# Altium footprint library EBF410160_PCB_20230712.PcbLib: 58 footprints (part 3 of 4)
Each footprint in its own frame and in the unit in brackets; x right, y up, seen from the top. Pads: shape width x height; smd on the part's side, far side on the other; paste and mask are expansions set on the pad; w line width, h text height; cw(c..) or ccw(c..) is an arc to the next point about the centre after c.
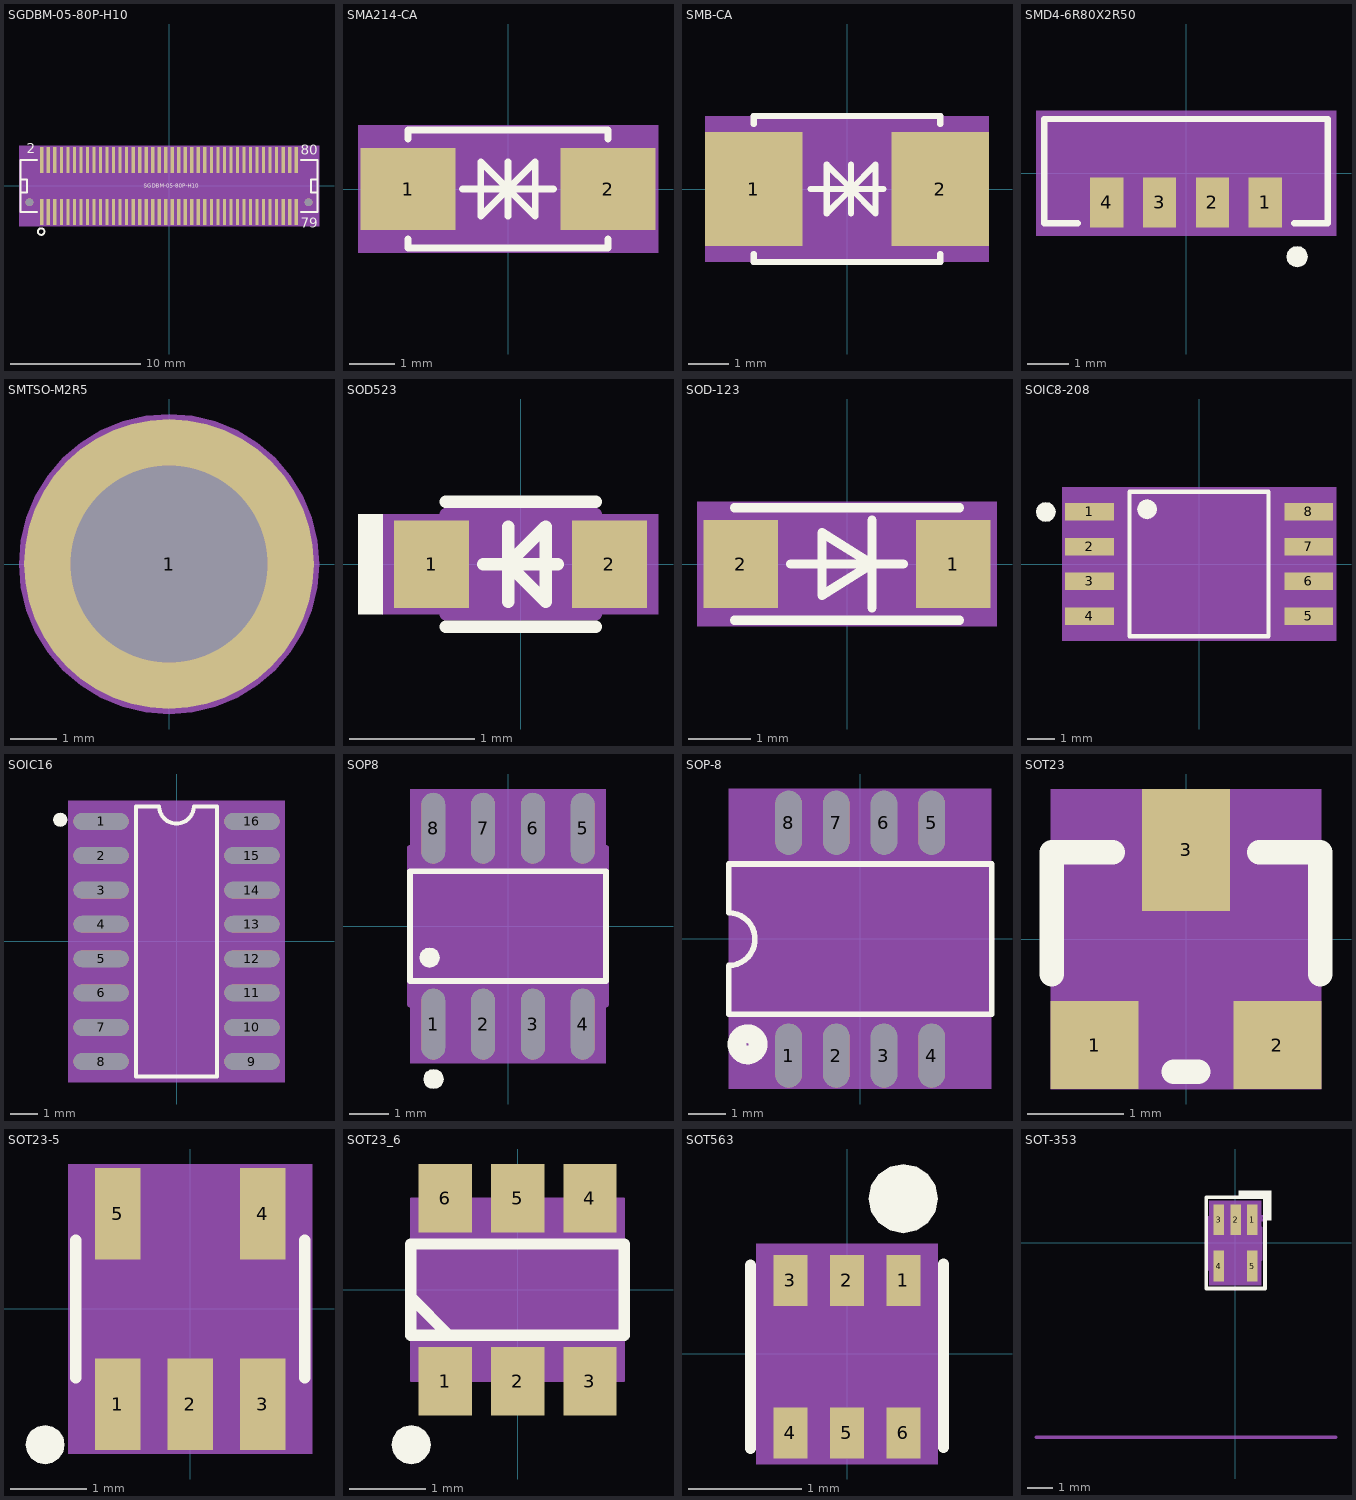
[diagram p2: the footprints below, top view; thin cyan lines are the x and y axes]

## SGDBM-05-80P-H10 [mm] "SGDBM-05-80P-H10"
pads (82):
  rect 0.25x2 smd: 1(-9.75,-2) 2(-9.75,2) 3(-9.25,-2) 4(-9.25,2) 5(-8.75,-2) 6(-8.75,2) 7(-8.25,-2) 8(-8.25,2) 9(-7.75,-2) 10(-7.75,2) 11(-7.25,-2) 12(-7.25,2) 13(-6.75,-2) 14(-6.75,2) 15(-6.25,-2) 16(-6.25,2) 17(-5.75,-2) 18(-5.75,2) 19(-5.25,-2) 20(-5.25,2) 21(-4.75,-2) 22(-4.75,2) 23(-4.25,-2) 24(-4.25,2) 25(-3.75,-2) 26(-3.75,2) 27(-3.25,-2) 28(-3.25,2) 29(-2.75,-2) 30(-2.75,2) 31(-2.25,-2) 32(-2.25,2) 33(-1.75,-2) 34(-1.75,2) 35(-1.25,-2) 36(-1.25,2) 37(-0.75,-2) 38(-0.75,2) 39(-0.25,-2) 40(-0.25,2) 41(0.25,-2) 42(0.25,2) 43(0.75,-2) 44(0.75,2) 45(1.25,-2) 46(1.25,2) 47(1.75,-2) 48(1.75,2) 49(2.25,-2) 50(2.25,2) 51(2.75,-2) 52(2.75,2) 53(3.25,-2) 54(3.25,2) 55(3.75,-2) 56(3.75,2) 57(4.25,-2) 58(4.25,2) 59(4.75,-2) 60(4.75,2) 61(5.25,-2) 62(5.25,2) 63(5.75,-2) 64(5.75,2) 65(6.25,-2) 66(6.25,2) 67(6.75,-2) 68(6.75,2) 69(7.25,-2) 70(7.25,2) 71(7.75,-2) 72(7.75,2) 73(8.25,-2) 74(8.25,2) 75(8.75,-2) 76(8.75,2) 77(9.25,-2) 78(9.25,2) 79(9.75,-2) 80(9.75,2)
  round 0.6 hole 0.6 unplated: ""(-10.7,-1.25) ""(10.7,-1.25)
Top Overlay:
  circle w0.15: c-9.8,-3.5 r0.25
  lines w0.15: -11.4,0 -11.4,-0.5 -10.9,-0.5 -10.9,0.5 -11.4,0.5 ; -10.1,-2 -11.4,-2 -11.4,2 -10.1,2 ; 10.1,-2 11.4,-2 11.4,2 10.1,2 ; 11.4,0 11.4,-0.5 10.9,-0.5 10.9,0.5 11.4,0.5
  text "80" at 10.113,2.399 h0.76
  text "79" at 10.113,-3.189 h0.76
  text "2" at -10.893,2.526 h0.76
  text "SGDBM-05-80P-H10" at -1.951,-0.152 h0.3
Top 3D Body:
  region: -11.5,3.1 -11.5,-3.1 11.5,-3.1 11.5,3.1
Mechanical 20:
  text "1" at -10.004,-2 h0.64
  text "3" at -9.504,-2 h0.64
  text "5" at -9.004,-2 h0.64
  text "2" at -10.004,2 h0.64
  text "4" at -9.504,2 h0.64
  text "6" at -9.004,2 h0.64
  text "38" at -1.258,2 h0.64
  text "34" at -2.258,2 h0.64
  text "36" at -1.758,2 h0.64
  text "80" at 9.242,2 h0.64
  text "46" at 0.742,2 h0.64
  text "28" at -3.758,2 h0.64
  text "25" at -4.258,-2 h0.64
  text "22" at -5.258,2 h0.64
  text "24" at -4.758,2 h0.64
  text "48" at 1.242,2 h0.64
  text "30" at -3.258,2 h0.64
  text "54" at 2.742,2 h0.64
  text "60" at 4.242,2 h0.64
  text "58" at 3.742,2 h0.64
  text "64" at 5.242,2 h0.64
  text "62" at 4.742,2 h0.64
  text "11" at -7.758,-2 h0.64
  text "13" at -7.258,-2 h0.64
  text "52" at 2.242,2 h0.64
  text "15" at -6.758,-2 h0.64
  text "17" at -6.258,-2 h0.64
  text "19" at -5.758,-2 h0.64
  text "21" at -5.258,-2 h0.64
  text "12" at -7.758,2 h0.64
  text "14" at -7.258,2 h0.64
  text "44" at 0.242,2 h0.64
  text "29" at -3.258,-2 h0.64
  text "42" at -0.258,2 h0.64
  text "7" at -8.504,-2 h0.64
  text "9" at -8.004,-2 h0.64
  text "23" at -4.758,-2 h0.64
  text "31" at -2.758,-2 h0.64
  text "49" at 1.742,-2 h0.64
  text "67" at 6.242,-2 h0.64
  text "73" at 7.742,-2 h0.64
  text "8" at -8.504,2 h0.64
  text "10" at -8.258,2 h0.64
  text "16" at -6.758,2 h0.64
  text "20" at -5.758,2 h0.64
  text "26" at -4.258,2 h0.64
  text "32" at -2.758,2 h0.64
  text "40" at -0.758,2 h0.64
  text "50" at 1.742,2 h0.64
  text "56" at 3.242,2 h0.64
  text "66" at 5.742,2 h0.64
  text "76" at 8.242,2 h0.64
  text "39" at -0.758,-2 h0.64
  text "78" at 8.742,2 h0.64
  text "45" at 0.742,-2 h0.64
  text "18" at -6.258,2 h0.64
  text "27" at -3.758,-2 h0.64
  text "37" at -1.258,-2 h0.64
  text "79" at 9.242,-2 h0.64
  text "77" at 8.742,-2 h0.64
  text "75" at 8.242,-2 h0.64
  text "74" at 7.742,2 h0.64
  text "72" at 7.242,2 h0.64
  text "71" at 7.242,-2 h0.64
  text "70" at 6.742,2 h0.64
  text "69" at 6.742,-2 h0.64
  text "68" at 6.242,2 h0.64
  text "65" at 5.742,-2 h0.64
  text "63" at 5.242,-2 h0.64
  text "61" at 4.742,-2 h0.64
  text "59" at 4.242,-2 h0.64
  text "57" at 3.742,-2 h0.64
  text "55" at 3.242,-2 h0.64
  text "53" at 2.742,-2 h0.64
  text "51" at 2.242,-2 h0.64
  text "33" at -2.258,-2 h0.64
  text "43" at 0.242,-2 h0.64
  text "41" at -0.258,-2 h0.64
  text "35" at -1.758,-2 h0.64
  text "47" at 1.242,-2 h0.64
Top Assembly:
  lines w0.15: -11.4,-2 -11.4,2 11.4,2 11.4,-2 -11.4,-2
3D body: height 3.81, standoff 0, extent -11.5,-3.1 11.5,3.1

## SMA214-CA [mm] "SMA214-CA"
pads (2):
  rect 2.1x1.8 smd: 1(-2.2,0) 2(2.2,0)
Top Overlay:
  lines w0.15: -2.2,-1.1 -2.2,-1.3 2.2,-1.3 2.2,-1.1 ; -2.2,1.1 -2.2,1.3 2.2,1.3 2.2,1.1 ; -1,0 1,0 ; 0,-0.6 0,0.6 ; 0,0 0.6,-0.6 0.6,0.6 0,0 ; 0,0 -0.6,0.6 -0.6,-0.6 0,0
Top 3D Body:
  region: -3.3,1.4 -3.3,-1.4 3.3,-1.4 3.3,1.4
Mechanical 20:
  text "1" at -1.946,0 h0.64
  text "2" at 2.454,0 h0.64
Top Assembly:
  lines w0.15: -2.2,-1.25 -2.2,1.25 2.2,1.25 2.2,-1.25 -2.2,-1.25
3D body: height 3.81, standoff 0, extent -3.3,-1.4 3.3,1.4

## SMB-CA [mm] "SMB-CA"
pads (2):
  rect 2.4x2.8 smd: 1(-2.3,0) 2(2.3,0)
Top Overlay:
  lines w0.15: -2.3,-1.6 -2.3,-1.8 2.3,-1.8 2.3,-1.6 ; -2.3,1.6 -2.3,1.8 2.3,1.8 2.3,1.6 ; -0.9,0 0.9,0 ; 0.1,0 -0.5,0.6 -0.5,-0.6 0.1,0 ; 0.1,0 0.7,-0.6 0.7,0.6 0.1,0 ; 0.1,-0.6 0.1,0.6 0.1,-0.6
Top 3D Body:
  region: -3.5,1.8 -3.5,-1.8 3.5,-1.8 3.5,1.8
Mechanical 20:
  text "2" at 2.3,0.254 h0.64
  text "1" at -2.3,0.254 h0.64
Top Assembly:
  lines w0.15: -2.3,-1.8 -2.3,1.8 2.3,1.8 2.3,-1.8 -2.3,-1.8
3D body: height 3.81, standoff 0, extent -3.5,-1.8 3.5,1.8

## SMD4-6R80X2R50 [mm] "SMD4-6R80X2R50"
pads (4):
  rect 0.8x1.2 smd: 1(1.905,-0.7) 2(0.635,-0.7) 3(-0.635,-0.7) 4(-1.905,-0.7)
Top Overlay:
  dashed: 2.412,-2.002 2.431,-2.1 2.487,-2.182 2.569,-2.238 2.667,-2.257 2.764,-2.238 2.792,-2.219 2.847,-2.182 2.902,-2.1 2.922,-2.002 2.902,-1.904 2.847,-1.822 2.792,-1.785 2.764,-1.766 2.667,-1.747 2.569,-1.766 2.487,-1.822 2.431,-1.904
  lines w0.15: -2.6,-1.2 -3.4,-1.2 -3.4,1.3 3.4,1.3 3.4,-1.2 2.6,-1.2
Top 3D Body:
  region: -3.6,1.5 -3.6,-1.5 3.6,-1.5 3.6,1.5
Mechanical 20:
  text "2" at 0.889,-0.7 h0.64
  text "3" at -0.381,-0.7 h0.64
  text "4" at -1.651,-0.7 h0.64
  text "1" at 2.159,-0.7 h0.64
Top Assembly:
  lines w0.15: -3.4,-1.2 -3.4,1.3 3.4,1.3 3.4,-1.2 -3.4,-1.2
3D body: height 3.81, standoff 0, extent -3.6,-1.5 3.6,1.5

## SMTSO-M2R5 [mm] "SMTSO-M2R5"
pads (1):
  round 6.2 / inner round 5.2 / far side round 5.2 hole 4.22: 1(0,0)
Top Overlay:
  text "M2.5X4mm" at -0.94,0.646 h0.3
Top Paste:
  dashed: 3.074,0.4 2.072,0.4 2.029,0.579 1.971,0.754 1.898,0.923 1.81,1.084 1.709,1.238 1.594,1.382 1.468,1.516 1.33,1.638 1.182,1.748 1.025,1.844 0.861,1.926 0.689,1.994 0.513,2.047 0.4,2.072 0.4,3.074 0.666,3.028 0.928,2.958 1.182,2.866 1.427,2.752 1.662,2.617 1.883,2.462 2.091,2.289 2.282,2.098 2.457,1.891 2.612,1.67 2.748,1.436 2.862,1.191 2.955,0.937 3.026,0.676 3.073,0.409
  dashed: 0.4,-3.074 0.4,-2.072 0.579,-2.029 0.754,-1.971 0.923,-1.898 1.084,-1.81 1.238,-1.709 1.382,-1.594 1.516,-1.468 1.638,-1.33 1.748,-1.182 1.844,-1.025 1.926,-0.861 1.994,-0.689 2.047,-0.513 2.072,-0.4 3.074,-0.4 3.028,-0.666 2.958,-0.928 2.866,-1.182 2.752,-1.427 2.617,-1.662 2.462,-1.883 2.289,-2.091 2.098,-2.282 1.891,-2.457 1.67,-2.612 1.436,-2.748 1.191,-2.862 0.937,-2.955 0.676,-3.026 0.409,-3.073
  dashed: -3.074,-0.4 -2.072,-0.4 -2.029,-0.579 -1.971,-0.754 -1.898,-0.923 -1.81,-1.084 -1.709,-1.238 -1.594,-1.382 -1.468,-1.516 -1.33,-1.638 -1.182,-1.748 -1.025,-1.844 -0.861,-1.926 -0.689,-1.994 -0.513,-2.047 -0.4,-2.072 -0.4,-3.074 -0.666,-3.028 -0.928,-2.958 -1.182,-2.866 -1.427,-2.752 -1.662,-2.617 -1.883,-2.462 -2.091,-2.289 -2.282,-2.098 -2.457,-1.891 -2.612,-1.67 -2.748,-1.436 -2.862,-1.191 -2.955,-0.937 -3.026,-0.676 -3.073,-0.409
  dashed: -0.4,3.074 -0.4,2.072 -0.579,2.029 -0.754,1.971 -0.923,1.898 -1.084,1.81 -1.238,1.709 -1.382,1.594 -1.516,1.468 -1.638,1.33 -1.748,1.182 -1.844,1.025 -1.926,0.861 -1.994,0.689 -2.047,0.513 -2.072,0.4 -3.074,0.4 -3.028,0.666 -2.958,0.928 -2.866,1.182 -2.752,1.427 -2.617,1.662 -2.462,1.883 -2.289,2.091 -2.098,2.282 -1.891,2.457 -1.67,2.612 -1.436,2.748 -1.191,2.862 -0.937,2.955 -0.676,3.026 -0.409,3.073
Top 3D Body:
  region: 3.21,0 3.17,0.502 3.053,0.992 2.86,1.457 2.597,1.887 2.27,2.27 1.887,2.597 1.457,2.86 0.992,3.053 0.502,3.17 0,3.21 -0.502,3.17 -0.992,3.053 -1.457,2.86 -1.601,2.772 -1.887,2.597 -2.27,2.27 -2.597,1.887 -2.86,1.457 -3.053,0.992 -3.17,0.502 -3.21,0 -3.17,-0.502 -3.053,-0.992 -2.86,-1.457 -2.597,-1.887 -2.27,-2.27 -1.887,-2.597 -1.601,-2.772 -1.457,-2.86 -0.992,-3.053 -0.502,-3.17 0,-3.21 0.502,-3.17 0.992,-3.053 1.457,-2.86 1.887,-2.597 2.27,-2.27 2.597,-1.887 2.86,-1.457 3.053,-0.992 3.17,-0.502
Mechanical 20:
  text "1" at -0.254,0 h0.64
Top Assembly:
  circle w0.025: c0,0 r3.1
3D body: height 3.81, standoff 0, extent -3.21,-3.21 3.21,3.21

## SOD523 [mm] "SOD523"
pads (2):
  rect 0.6x0.7 smd: 1(-0.71,0) 2(0.71,0)
Top Overlay:
  dashed: -1.3,0.4 -1.3,-0.4 -1.1,-0.4 -1.1,0.4
  lines w0.1: -0.6,-0.5 0.6,-0.5 ; -0.6,0.5 0.6,0.5 ; -0.3,0 0.3,0 ; -0.1,-0.3 -0.1,0.3 ; -0.1,0 0.2,-0.3 0.2,0.3 -0.1,0
Top 3D Body:
  region: -1.1,0.4 -1.1,-0.4 1.1,-0.4 1.1,0.4
Mechanical 20:
  text "1" at -0.964,0 h0.64
  text "2" at 0.456,0 h0.64
Top Assembly:
  lines w0.1: -0.6,-0.4 -0.6,0.4 0.6,0.4 0.6,-0.4 -0.6,-0.4
3D body: height 3.81, standoff 0, extent -1.1,-0.4 1.1,0.4

## SOD-123 [mm] "SOD-123"
pads (2):
  rect 1.2x1.4 smd: 1(1.7,0) 2(-1.7,0)
Top Overlay:
  lines w0.15: -1.8,-0.9 1.8,-0.9 ; -1.8,0.9 1.8,0.9 ; -0.9,0 0.9,0 ; 0.4,-0.7 0.4,0.7 ; -0.4,-0.5 -0.4,0.5 0.4,0 -0.4,-0.5
Top 3D Body:
  region: -2.4,-1 2.4,-1 2.4,1 -2.4,1
Mechanical 20:
  text "1" at 1.7,-0.315 h0.79
  text "2" at -1.7,-0.315 h0.79
Top Assembly:
  lines w0.15: -1.8,-0.9 1.8,-0.9 1.8,0.9 -1.8,0.9 -1.8,-0.9
3D body: height 3.81, standoff 0, extent -2.4,-1 2.4,1

## SOIC8-208 [mm] "SOIC8-208"
pads (8):
  rect 1.778x0.635 smd: 1(-4,1.905) 2(-4,0.635) 3(-4,-0.635) 4(-4,-1.905) 5(4,-1.905) 6(4,-0.635) 7(4,0.635) 8(4,1.905)
Top Overlay:
  dashed: -5.6,2.257 -5.737,2.23 -5.852,2.152 -5.93,2.037 -5.957,1.9 -5.93,1.763 -5.904,1.725 -5.852,1.648 -5.737,1.57 -5.6,1.543 -5.463,1.57 -5.348,1.648 -5.296,1.725 -5.27,1.763 -5.243,1.9 -5.27,2.037 -5.348,2.152 -5.463,2.23
  dashed: -1.9,2.357 -2.037,2.33 -2.152,2.252 -2.23,2.137 -2.257,2 -2.23,1.863 -2.204,1.825 -2.152,1.748 -2.037,1.67 -1.9,1.643 -1.763,1.67 -1.648,1.748 -1.596,1.825 -1.57,1.863 -1.543,2 -1.57,2.137 -1.648,2.252 -1.763,2.33
  lines w0.152: -2.54,-2.64 2.54,-2.64 2.54,2.64 -2.54,2.64 -2.54,-2.64
Top 3D Body:
  region: -5,2.8 -5,-2.8 5,-2.8 5,2.8
Mechanical 20:
  text "4" at -4,-2.108 h0.51
  text "8" at 4,1.702 h0.51
  text "7" at 4,0.432 h0.51
  text "3" at -4,-0.838 h0.51
  text "2" at -4,0.432 h0.51
  text "5" at 4,-2.108 h0.51
  text "6" at 4,-0.838 h0.51
  text "1" at -4,1.702 h0.51
Top Assembly:
  lines w0.152: -2.54,-2.64 2.54,-2.64 2.54,2.64 -2.54,2.64 -2.54,-2.64
3D body: height 3.81, standoff 0, extent -5,-2.8 5,2.8

## SOIC16 [mil] "SOIC16"
pads (16):
  oval 80x24 smd: 1(-109.8,174.8) 2(-109.8,125.2) 3(-109.8,74.8) 4(-109.8,25.2) 5(-109.8,-25.2) 6(-109.8,-74.8) 7(-109.8,-125.2) 8(-109.8,-174.8) 9(109.8,-174.8) 10(109.8,-125.2) 11(109.8,-74.8) 12(109.8,-25.2) 13(109.8,25.2) 14(109.8,74.8) 15(109.8,125.2) 16(109.8,174.8)
Top Overlay:
  dashed: -169.29,167.13 -173.13,167.89 -176.39,170.07 -178.56,173.32 -179.33,177.16 -178.56,181.01 -177.83,182.1 -176.39,184.26 -173.13,186.44 -169.29,187.2 -165.45,186.44 -162.2,184.26 -160.75,182.1 -160.02,181.01 -159.26,177.16 -160.02,173.32 -162.2,170.07 -165.45,167.89
  lines w5.91: -59.05,-196.85 59.05,-196.85 59.05,196.85 25.2,196.85 cw(c0,196.85) -25.2,196.85 -39.37,196.85 -59.05,196.85 -59.05,-196.85
Top 3D Body:
  region: -157.48,204.72 -157.48,-204.72 157.48,-204.72 157.48,204.72
Mechanical 20:
  text "8" at -109.8,-170.08 h11.8
  text "13" at 109.8,34.64 h11.8
  text "14" at 109.8,84.24 h11.8
  text "7" at -109.8,-120.48 h11.8
  text "15" at 109.8,134.64 h11.8
  text "16" at 109.8,184.24 h11.8
  text "1" at -109.8,179.52 h11.8
  text "3" at -109.8,79.52 h11.8
  text "12" at 109.8,-15.76 h11.8
  text "9" at 109.8,-170.08 h11.8
  text "10" at 109.8,-115.76 h11.8
  text "4" at -109.8,29.92 h11.8
  text "11" at 109.8,-65.36 h11.8
  text "5" at -109.8,-20.48 h11.8
  text "6" at -109.8,-70.08 h11.8
  text "2" at -109.8,129.92 h11.8
3D body: height 150, standoff 0, extent -157.48,-204.72 157.48,204.72

## SOP8 [mm] "SOP8"
pads (8):
  oval 0.6x1.8 smd: 1(-1.905,-2.5) 2(-0.635,-2.5) 3(0.635,-2.5) 4(1.905,-2.5) 5(1.905,2.5) 6(0.635,2.5) 7(-0.635,2.5) 8(-1.905,2.5)
Top Overlay:
  dashed: -1.745,-0.8 -1.765,-0.898 -1.82,-0.98 -1.902,-1.035 -2,-1.055 -2.098,-1.035 -2.125,-1.017 -2.18,-0.98 -2.235,-0.898 -2.255,-0.8 -2.235,-0.702 -2.18,-0.62 -2.125,-0.583 -2.098,-0.565 -2,-0.545 -1.902,-0.565 -1.82,-0.62 -1.765,-0.702
  dashed: -1.645,-3.9 -1.665,-3.998 -1.72,-4.08 -1.802,-4.135 -1.9,-4.155 -1.998,-4.135 -2.025,-4.117 -2.08,-4.08 -2.135,-3.998 -2.155,-3.9 -2.135,-3.802 -2.08,-3.72 -2.025,-3.683 -1.998,-3.665 -1.9,-3.645 -1.802,-3.665 -1.72,-3.72 -1.665,-3.802
  lines w0.15: -2.5,-1.4 -2.5,1.4 2.5,1.4 2.5,-1.4 -2.5,-1.4
Top 3D Body:
  region: -2.5,3.5 -2.5,-3.5 2.5,-3.5 2.5,3.5
Mechanical 20:
  text "1" at -2.159,-2.5 h0.64
  text "4" at 1.651,-2.5 h0.64
  text "7" at -0.889,2.5 h0.64
  text "6" at 0.381,2.5 h0.64
  text "5" at 1.651,2.5 h0.64
  text "8" at -2.159,2.5 h0.64
  text "2" at -0.889,-2.5 h0.64
  text "3" at 0.381,-2.5 h0.64
Top Assembly:
  lines w0.15: -2.5,-2 -2.5,2 2.5,2 2.5,-2 -2.5,-2
3D body: height 3.81, standoff 0, extent -2.5,-3.5 2.5,3.5

## SOP-8 [mm] "SOP-8"
pads (8):
  oval 0.7x1.7 smd: 1(-1.903,-3.104) 2(-0.633,-3.104) 3(0.637,-3.104) 4(1.907,-3.104) 5(1.907,3.096) 6(0.637,3.096) 7(-0.633,3.096) 8(-1.903,3.096)
Top Overlay:
  circle w0.5: c-2.998,-2.804 r0.283
  lines w0.15: -3.498,-2.004 3.502,-2.004 3.502,1.996 -3.498,1.996 -3.498,0.696 cw(c-3.498,-0.004) -3.498,-0.704 -3.498,-2.004
Top 3D Body:
  region: 3.498,-3.994 3.498,3.994 -3.498,3.994 -3.498,-3.994
Mechanical 20:
  text "8" at -1.903,3.269 h0.43
  text "7" at -0.633,3.269 h0.43
  text "3" at 0.637,-2.931 h0.43
  text "6" at 0.637,3.269 h0.43
  text "5" at 1.907,3.269 h0.43
  text "4" at 1.907,-2.931 h0.43
  text "2" at -0.633,-2.931 h0.43
  text "1" at -1.903,-2.931 h0.43
3D body: height 3.81, standoff 0, extent -3.498,-3.994 3.498,3.994

## SOT23 [mil] "SOT23"
pads (3):
  rect 36x36 smd: 1(-37.5,-43.5) 2(37.5,-43.5)
  rect 36x50 smd: 3(0,36.5)
Top Overlay:
  lines w10: -55,-14.5 -55,35.5 -30,35.5 ; -5,-54.5 5,-54.5 ; 30,35.5 55,35.5 55,-14.5
Top 3D Body:
  region: -55.5,-61.5 55.5,-61.5 55.5,61.5 -55.5,61.5
Mechanical 20:
  text "1" at -37.5,-61.5 h45
  text "3" at 0,18.5 h45
  text "2" at 37.5,-61.5 h45
3D body: height 150, standoff 0, extent -55.5,-61.5 55.5,61.5

## SOT23-5 [mm] "SOT23-5"
pads (5):
  rect 0.599x1.199 smd: 1(-0.95,-1.25) 2(0,-1.25) 3(0.95,-1.25) 4(0.95,1.25) 5(-0.95,1.25)
Top Overlay:
  dashed: -1.905,-2.033 -2.003,-2.013 -2.085,-1.958 -2.14,-1.876 -2.16,-1.778 -2.14,-1.68 -2.122,-1.653 -2.085,-1.598 -2.003,-1.543 -1.905,-1.523 -1.807,-1.543 -1.725,-1.598 -1.688,-1.653 -1.67,-1.68 -1.65,-1.778 -1.67,-1.876 -1.725,-1.958 -1.807,-2.013
  lines w0.15: -1.5,-0.9 -1.5,0.9 ; 1.5,-0.9 1.5,0.9
Top 3D Body:
  region: -1.6,1.9 -1.6,-1.9 1.6,-1.9 1.6,1.9
Mechanical 20:
  text "5" at -0.95,1.29 h0.1
  text "2" at 0,-1.21 h0.1
  text "3" at 0.95,-1.21 h0.1
  text "4" at 0.95,1.29 h0.1
  text "1" at -0.95,-1.21 h0.1
Top Assembly:
  lines w0.15: -1.5,-0.85 -1.5,0.85 1.5,0.85 1.5,-0.85 -1.5,-0.85
3D body: height 3.81, standoff 0, extent -1.6,-1.9 1.6,1.9

## SOT23_6 [mm] "SOT23_6"
pads (6):
  rect 0.7x0.9 smd: 1(-0.95,-1.2) 2(0,-1.2) 3(0.95,-1.2) 4(0.95,1.2) 5(0,1.2) 6(-0.95,1.2)
Top Overlay:
  dashed: -1.397,-2.287 -1.495,-2.268 -1.577,-2.212 -1.633,-2.13 -1.652,-2.032 -1.633,-1.934 -1.614,-1.907 -1.577,-1.852 -1.495,-1.796 -1.397,-1.777 -1.299,-1.796 -1.217,-1.852 -1.18,-1.907 -1.161,-1.934 -1.142,-2.032 -1.161,-2.13 -1.217,-2.212 -1.299,-2.268
  lines w0.15: -1.4,-0.1 -0.9,-0.6 ; -1.4,-0.6 1.4,-0.6 1.4,0.6 -1.4,0.6 -1.4,-0.6
Top 3D Body:
  region: -1.4,-1.2 -1.4,1.2 1.4,1.2 1.4,-1.2
Mechanical 20:
  text "3" at 0.95,-0.946 h0.64
  text "6" at -0.95,1.454 h0.64
  text "2" at 0,-0.946 h0.64
  text "5" at 0,1.454 h0.64
  text "4" at 0.95,1.454 h0.64
  text "1" at -0.95,-0.946 h0.64
Top Assembly:
  lines w0.025: -1.4,-1.2 1.4,-1.2 1.4,1.2 -1.4,1.2 -1.4,-1.2
3D body: height 3.81, standoff 0, extent -1.4,-1.2 1.4,1.2

## SOT563 [mm] "SOT563"
pads (6):
  rect 0.3x0.45 smd: 1(0.499,0.65) 2(-0.001,0.65) 3(-0.501,0.65) 4(-0.501,-0.7) 5(-0.001,-0.7) 6(0.499,-0.7)
Top Overlay:
  dashed: 0.805,1.375 0.781,1.258 0.715,1.159 0.616,1.092 0.499,1.069 0.382,1.092 0.349,1.115 0.283,1.159 0.216,1.258 0.193,1.375 0.216,1.492 0.283,1.591 0.349,1.635 0.382,1.658 0.499,1.681 0.616,1.658 0.715,1.591 0.781,1.492
  lines w0.1: -0.854,-0.837 -0.854,0.785 ; 0.854,-0.826 0.854,0.796
Top 3D Body:
  region: 0.804,0.975 -0.804,0.975 -0.804,-0.975 0.804,-0.975
Mechanical 20:
  text "3" at -0.741,0.65 h0.3
  text "5" at -0.241,-0.7 h0.3
  text "6" at 0.259,-0.7 h0.3
  text "4" at -0.741,-0.7 h0.3
  text "2" at -0.241,0.65 h0.3
  text "1" at 0.259,0.65 h0.3
3D body: height 3.81, standoff 0, extent -0.804,-0.975 0.804,0.975

## SOT-353 [mil] "SOT-353"
pads (5):
  rect 16x47 smd: 1(25.91,35.43) 2(0.32,35.43) 3(-25.28,35.43) 4(-25.28,-35.43) 5(25.91,-35.43)
Top Overlay:
  dashed: 45.31,35 55.31,35 55.31,80 5.32,80 5.32,70 45.31,70
  lines w6: -44.69,-70 -44.69,70 45.31,70 45.31,-70 -44.69,-70
Top Courtyard:
  dashed: 39.69,65 -39.69,65 -39.69,-65 39.69,-65
Top 3D Body:
  region: 39.69,65 -39.69,65 -39.69,-65 39.69,-65
Mechanical 9:
  circle w1: c0.32,0 r11.81
  circle w1: c0.32,0 r11.81
  lines w1: -15.43,0 16.06,0 -15.43,0 ; 0.32,-15.75 0.32,15.75 0.32,-15.75
Mechanical 20:
  text "2" at -6.08,35.43 h16
  text "3" at -31.68,35.43 h16
  text "1" at 19.51,35.43 h16
  text "5" at 19.51,-35.43 h16
  text "4" at -31.68,-35.43 h16
Top Assembly:
  circle w3.94: c41.31,38 r2.83
  lines w3.94: -31.68,-26 -31.68,-41.83 -19.68,-41.83 ; -31.68,24 -31.68,40 ; -31.68,40.83 -19.68,40.83 -19.68,24 ; -19.68,-41 -19.68,-26 ; -5.68,24 -5.68,40 ; -5.68,40.83 6.32,40.83 6.32,24 ; 19.5,-26 19.5,-41.83 31.5,-41.83 ; 20.32,25 20.32,40 ; 20.32,40.83 32.31,40.83 32.31,24 ; 31.5,-40.83 31.5,-26 ; -40.69,-25.61 -40.69,23.61 39.31,23.61 39.31,-25.61 -40.69,-25.61
Mechanical 24:
  lines w5: -305.69,-298 154.31,-298
  text "Sofer Lib Information" at 154.31,-308 h25
  text "Ref PN: ESDALC6V1W5" at 124.31,-258 h25
  text "Creat : Yuki" at 124.31,-218 h25
  text "Date  : 2007-11-30" at 124.31,-178 h25
  text "Rev   : A1" at 124.31,-138 h25
  text "Remark: ***" at 124.31,-98 h25
Mechanical 26:
  lines w1: -40.69,-42 -40.69,41 39.31,41 39.31,-42 -40.69,-42
Mechanical 27:
  text "Approved" at -111.69,0 h35
Mechanical 28:
  text "SOT-353" at -88.69,163 h30
3D body: height 150, standoff 0, extent -39.69,-65 39.69,65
